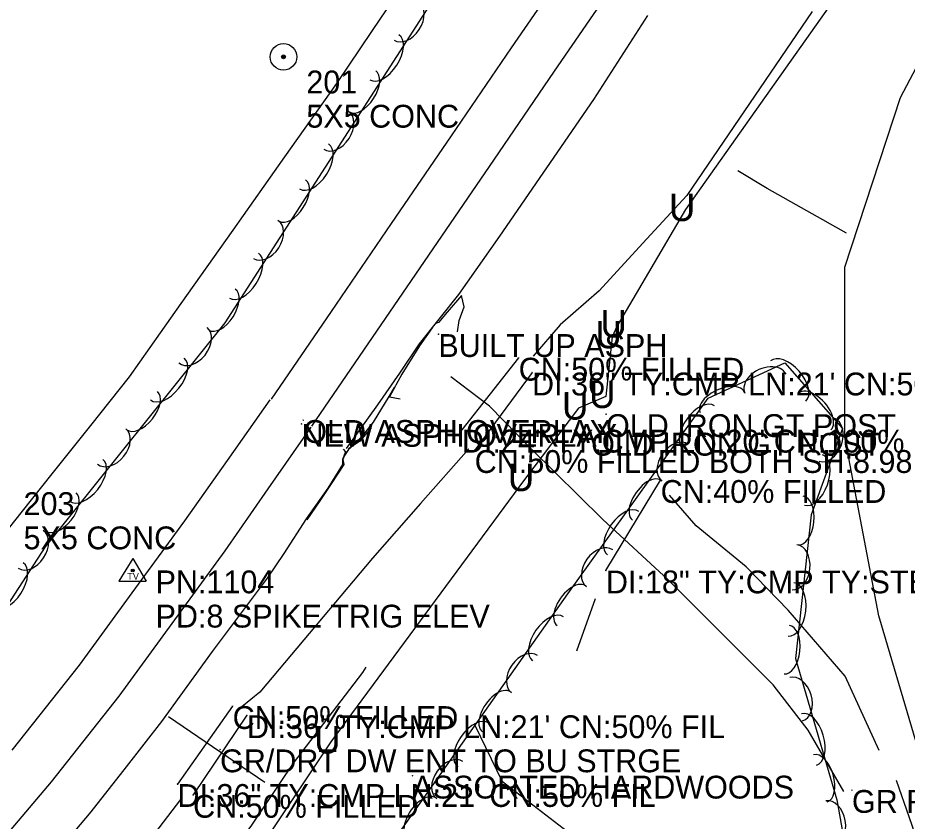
# Model space of a CAD drawing. Extents: x 1451369 to 1458940, y 1868647 to 1875095.
# Drawn here: x 1454748.2 to 1454943, y 1871825.9 to 1872001.9 of the extents above; entities that cross this region are included whole.
import ezdxf

# ---------------------------------------------------------------- set-up
doc = ezdxf.new("R2010")
doc.units = 0
for name, color, linetype in [('Default', 7, 'Continuous'), ('E_Const Align Station', 7, 'Continuous'), ('E_PL and Hook', 7, 'Continuous'), ('E_Proposed ROW and Easements', 7, 'Continuous'), ('E_ROW Point Number', 7, 'Continuous'), ('E_Station Offset', 7, 'Continuous'), ('E_Survey Point', 7, 'Continuous'), ('E_Survey Point Number', 7, 'Continuous'), ('E_Tract Number', 7, 'Continuous'), ('E_Tract Residual', 7, 'Continuous'), ('S_EDGE_PAVEMENT', 7, 'Continuous'), ('S_EXIST_ROW', 7, 'Continuous'), ('S_IRON_PIN_ANNOT', 7, 'Continuous'), ('S_MISC_BOUNDARY', 7, 'Continuous'), ('S_MISC_STRUCTURES_ANNOT', 7, 'Continuous'), ('S_PAVEMENT_CROWN', 7, 'Continuous'), ('S_SECONDARY_CTL_ANNOT', 7, 'Continuous'), ('S_SIDE_DRAIN_ANNOT', 7, 'Continuous'), ('S_SURVEY_TEXT_ANNOT', 7, 'Continuous'), ('S_TRAILS', 7, 'Continuous')]:
    doc.layers.add(name, color=color, linetype=linetype)

msp = doc.modelspace()

# ---------------------------------------------------------------- linework, layer by layer
at = {"layer": 'E_Const Align Station'}
for radius in [2.91, 0.411, 0.262, 0.212, 0.145, 0.0822, 0.0581]:
    msp.add_circle((1454806.43, 1871993.3), radius, dxfattribs=at)
at = {"layer": 'E_PL and Hook'}
for p, q in [((1454857.92, 1871927.4), (1454845.49, 1871911.64)), ((1454860.85, 1871924.16), (1454848.29, 1871907.18)), ((1454877.04, 1871880.81), (1454889.02, 1871900.62)), ((1454795.28, 1871851.11), (1454783.2, 1871834.04)), ((1454798.42, 1871849.1), (1454786.63, 1871831.67))]:
    msp.add_line(p, q, dxfattribs=at)
at = {"layer": 'E_Proposed ROW and Easements'}
for points in [[(1454840.33, 1871932.58), (1454840.33, 1871932.63), (1454840.33, 1871932.58), (1454840.28, 1871932.58), (1454840.33, 1871932.58), (1454840.33, 1871932.53), (1454840.33, 1871932.58), (1454840.38, 1871932.58)], [(1454877.05, 1871915.05), (1454877.05, 1871915.1), (1454877.05, 1871915.05), (1454877, 1871915.05), (1454877.05, 1871915.05), (1454877.05, 1871915), (1454877.05, 1871915.05), (1454877.1, 1871915.05)], [(1454810.37, 1871912.91), (1454810.37, 1871912.96), (1454810.37, 1871912.91), (1454810.32, 1871912.91), (1454810.37, 1871912.91), (1454810.37, 1871912.86), (1454810.37, 1871912.91), (1454810.42, 1871912.91)], [(1454810.75, 1871913.76), (1454810.75, 1871913.81), (1454810.75, 1871913.76), (1454810.7, 1871913.76), (1454810.75, 1871913.76), (1454810.75, 1871913.71), (1454810.75, 1871913.76), (1454810.8, 1871913.76)], [(1454873.8, 1871910.97), (1454873.8, 1871911.02), (1454873.8, 1871910.97), (1454873.75, 1871910.97), (1454873.8, 1871910.97), (1454873.8, 1871910.92), (1454873.8, 1871910.97), (1454873.85, 1871910.97)], [(1454848.31, 1871847), (1454848.31, 1871847.05), (1454848.31, 1871847), (1454848.26, 1871847), (1454848.31, 1871847), (1454848.31, 1871846.95), (1454848.31, 1871847), (1454848.36, 1871847)], [(1454792.53, 1871841.63), (1454792.53, 1871841.68), (1454792.53, 1871841.63), (1454792.48, 1871841.63), (1454792.53, 1871841.63), (1454792.53, 1871841.58), (1454792.53, 1871841.63), (1454792.58, 1871841.63)], [(1454834.64, 1871835.87), (1454834.64, 1871835.92), (1454834.64, 1871835.87), (1454834.59, 1871835.87), (1454834.64, 1871835.87), (1454834.64, 1871835.82), (1454834.64, 1871835.87), (1454834.69, 1871835.87)], [(1454854.39, 1871834.51), (1454854.39, 1871834.56), (1454854.39, 1871834.51), (1454854.34, 1871834.51), (1454854.39, 1871834.51), (1454854.39, 1871834.46), (1454854.39, 1871834.51), (1454854.44, 1871834.51)], [(1454930.91, 1871832.74), (1454930.91, 1871832.79), (1454930.91, 1871832.74), (1454930.86, 1871832.74), (1454930.91, 1871832.74), (1454930.91, 1871832.69), (1454930.91, 1871832.74), (1454930.96, 1871832.74)]]:
    msp.add_lwpolyline(points, dxfattribs=at)
at = {"layer": 'E_ROW Point Number'}
for points in [[(1454838.97, 1872005.51), (1454793.59, 1871935.04), (1454754.24, 1871885.99), (1454738.31, 1871861.57)], [(1454866, 1871710.55), (1454881.19, 1871720.56), (1454870.77, 1871731.38), (1454848.07, 1871733.96), (1454825.2, 1871735.11), (1454799.89, 1871732.45), (1454789.97, 1871746.64), (1454796, 1871772.6), (1454868.67, 1871875.67), (1454899.4, 1871918.58), (1454916.25, 1871926.31), (1454928.84, 1871911.94), (1454921.96, 1871892.98), (1454918.57, 1871861.56), (1454927.6, 1871830.59), (1454936.01, 1871783.4), (1454940.39, 1871738.54), (1454943.46, 1871701.76)]]:
    msp.add_lwpolyline(points, dxfattribs=at)
for centre, major_axis, ratio, start_param, end_param in [((1454833.31, 1872001.13), (2.68, 4.17), 0.68525, 3.141593, 6.283185), ((1454828.52, 1871993.21), (3.18, 4.93), 0.550031, 3.141593, 6.283185), ((1454823.72, 1871985.75), (2.89, 4.5), 0.540651, 3.141593, 6.283185), ((1454817.92, 1871977.23), (2.68, 4.17), 0.68525, 3.141593, 6.283185), ((1454813.13, 1871969.3), (3.18, 4.93), 0.550031, 3.141593, 6.283185), ((1454808.33, 1871961.85), (2.89, 4.5), 0.540651, 3.141593, 6.283185), ((1454802.53, 1871953.33), (2.68, 4.17), 0.68525, 3.141593, 6.283185), ((1454797.74, 1871945.4), (3.18, 4.93), 0.550031, 3.141593, 6.283185), ((1454792.94, 1871937.95), (2.89, 4.5), 0.540651, 3.141593, 6.283185), ((1454786.59, 1871930.13), (3.1, 3.87), 0.685257, 3.141593, 6.283185), ((1454781, 1871922.74), (3.67, 4.58), 0.550037, 3.141593, 6.283185), ((1454916.93, 1871922.31), (-3.87, 4.41), 0.5501, 3.141567, 6.283159), ((1454911.97, 1871921.72), (-4.5, -2.07), 0.685217, 3.141379, 6.282972), ((1454902.5, 1871917.66), (-4.86, -2.23), 0.540626, 3.141466, 6.283059), ((1454922.77, 1871915.64), (-3.52, 4.02), 0.54072, 3.141567, 6.28316), ((1454775.45, 1871915.82), (3.35, 4.17), 0.540657, 3.141593, 6.283185), ((1454897.38, 1871912.11), (-3.42, -4.77), 0.550059, 3.141794, 6.283386), ((1454925.4, 1871909.44), (1.69, 4.66), 0.685239, 3.141593, 6.283185), ((1454768.8, 1871907.95), (3.1, 3.87), 0.685257, 3.141593, 6.283185), ((1454892.2, 1871904.43), (-2.89, -4.03), 0.685285, 3.141922, 6.283514), ((1454763.21, 1871900.57), (3.67, 4.58), 0.550037, 3.141593, 6.283185), ((1454922.49, 1871900.65), (2, 5.52), 0.550022, 3.141593, 6.283185), ((1454885.99, 1871896.21), (-3.11, -4.35), 0.540679, 3.141787, 6.28338), ((1454757.67, 1871893.65), (3.35, 4.17), 0.540657, 3.141593, 6.283185), ((1454919.69, 1871891.74), (0.57, 5.32), 0.540665, 3.141593, 6.283185), ((1454880.83, 1871889), (-3.42, -4.77), 0.550059, 3.141794, 6.283386), ((1454751.05, 1871885.46), (2.71, 4.15), 0.68525, 3.141593, 6.283185), ((1454875.65, 1871881.32), (-2.89, -4.03), 0.685285, 3.141922, 6.283514), ((1454918.33, 1871881.52), (0.53, 4.93), 0.685268, 3.141593, 6.283185), ((1454746.21, 1871877.56), (3.21, 4.92), 0.550031, 3.141593, 6.283185), ((1454869.46, 1871873.11), (-3.08, -4.37), 0.540631, 3.141676, 6.283269), ((1454917.59, 1871872.29), (0.63, 5.83), 0.550045, 3.141593, 6.283185), ((1454864.35, 1871865.86), (-3.38, -4.8), 0.55001, 3.141679, 6.283271), ((1454916.64, 1871863.47), (0.57, 5.32), 0.540665, 3.141593, 6.283185), ((1454859.22, 1871858.14), (-2.86, -4.05), 0.685224, 3.141734, 6.283326), ((1454918.69, 1871852.63), (-1.39, 4.76), 0.685303, 3.141593, 6.283185), ((1454853.07, 1871849.87), (-3.08, -4.37), 0.540631, 3.141676, 6.283269), ((1454921.53, 1871843.82), (-1.64, 5.63), 0.550074, 3.141593, 6.283185), ((1454847.97, 1871842.62), (-3.38, -4.8), 0.55001, 3.141679, 6.283271), ((1454924.01, 1871835.3), (-1.5, 5.13), 0.540694, 3.141593, 6.283185), ((1454842.84, 1871834.91), (-2.86, -4.05), 0.685224, 3.141734, 6.283326), ((1454836.69, 1871826.64), (-3.08, -4.37), 0.540631, 3.141676, 6.283269), ((1454926.09, 1871825.47), (-0.87, 4.88), 0.685298, 3.141572, 6.283164)]:
    msp.add_ellipse(centre, major_axis=major_axis, ratio=ratio, start_param=start_param, end_param=end_param, dxfattribs=at)
at = {"layer": 'E_Station Offset'}
for p, q in [((1454773.4, 1871883.43), (1454770.39, 1871878.47)), ((1454773.4, 1871883.43), (1454776.35, 1871878.47)), ((1454770.39, 1871878.47), (1454776.35, 1871878.47))]:
    msp.add_line(p, q, dxfattribs=at)
for radius in [0.311, 0.183, 0.103]:
    msp.add_circle((1454773.4, 1871880.82), radius, dxfattribs=at)
at = {"layer": 'E_Survey Point'}
for p, q in [((1454854.39, 1871834.51), (1454848.31, 1871847)), ((1454880.25, 1871814.68), (1454854.39, 1871834.51))]:
    msp.add_line(p, q, dxfattribs=at)
at = {"layer": 'E_Survey Point Number'}
for p, q in [((1455036.45, 1872160.65), (1454894.46, 1871959.88)), ((1454894.46, 1871959.88), (1454879.47, 1871934.42)), ((1454879.47, 1871934.42), (1454878.37, 1871932.01)), ((1454878.37, 1871932.01), (1454876.98, 1871918.94)), ((1454876.98, 1871918.94), (1454871.04, 1871916.4)), ((1454871.04, 1871916.4), (1454859.19, 1871900.75)), ((1454859.19, 1871900.75), (1454816.77, 1871843.27)), ((1454816.77, 1871843.27), (1454794.83, 1871810.44))]:
    msp.add_line(p, q, dxfattribs=at)
at = {"layer": 'E_Tract Number'}
for points in [[(1454857.92, 1871927.4), (1454857.92, 1871927.45), (1454857.92, 1871927.4), (1454857.87, 1871927.4), (1454857.92, 1871927.4), (1454857.92, 1871927.35), (1454857.92, 1871927.4), (1454857.97, 1871927.4)], [(1454860.85, 1871924.16), (1454860.85, 1871924.21), (1454860.85, 1871924.16), (1454860.8, 1871924.16), (1454860.85, 1871924.16), (1454860.85, 1871924.11), (1454860.85, 1871924.16), (1454860.9, 1871924.16)], [(1454845.49, 1871911.64), (1454845.49, 1871911.69), (1454845.49, 1871911.64), (1454845.44, 1871911.64), (1454845.49, 1871911.64), (1454845.49, 1871911.59), (1454845.49, 1871911.64), (1454845.54, 1871911.64)], [(1454848.29, 1871907.18), (1454848.29, 1871907.23), (1454848.29, 1871907.18), (1454848.24, 1871907.18), (1454848.29, 1871907.18), (1454848.29, 1871907.13), (1454848.29, 1871907.18), (1454848.34, 1871907.18)], [(1454889.02, 1871900.62), (1454889.02, 1871900.67), (1454889.02, 1871900.62), (1454888.97, 1871900.62), (1454889.02, 1871900.62), (1454889.02, 1871900.57), (1454889.02, 1871900.62), (1454889.07, 1871900.62)], [(1454877.04, 1871880.81), (1454877.04, 1871880.86), (1454877.04, 1871880.81), (1454876.99, 1871880.81), (1454877.04, 1871880.81), (1454877.04, 1871880.76), (1454877.04, 1871880.81), (1454877.09, 1871880.81)], [(1454795.28, 1871851.11), (1454795.28, 1871851.16), (1454795.28, 1871851.11), (1454795.23, 1871851.11), (1454795.28, 1871851.11), (1454795.28, 1871851.06), (1454795.28, 1871851.11), (1454795.33, 1871851.11)], [(1454798.42, 1871849.1), (1454798.42, 1871849.15), (1454798.42, 1871849.1), (1454798.37, 1871849.1), (1454798.42, 1871849.1), (1454798.42, 1871849.05), (1454798.42, 1871849.1), (1454798.47, 1871849.1)], [(1454783.2, 1871834.04), (1454783.2, 1871834.09), (1454783.2, 1871834.04), (1454783.15, 1871834.04), (1454783.2, 1871834.04), (1454783.2, 1871833.99), (1454783.2, 1871834.04), (1454783.25, 1871834.04)], [(1454786.63, 1871831.67), (1454786.63, 1871831.72), (1454786.63, 1871831.67), (1454786.58, 1871831.67), (1454786.63, 1871831.67), (1454786.63, 1871831.62), (1454786.63, 1871831.67), (1454786.68, 1871831.67)]]:
    msp.add_lwpolyline(points, dxfattribs=at)
at = {"layer": 'E_Tract Residual'}
msp.add_lwpolyline([(1454958.72, 1871739.79), (1454951.87, 1871790.34), (1454946.35, 1871818.45), (1454940.67, 1871834.81)], dxfattribs=at)
at = {"layer": 'S_EDGE_PAVEMENT'}
for points in [[(1454869.28, 1872014.16), (1454856.27, 1871995.25), (1454843.13, 1871976.02), (1454829.99, 1871956.78), (1454816.85, 1871937.55), (1454803.72, 1871918.32)], [(1454886.12, 1872002.39), (1454874.32, 1871984), (1454864.04, 1871969), (1454853.75, 1871954.01), (1454844.75, 1871941.26), (1454836.1, 1871930.43), (1454831.8, 1871924.05), (1454826.99, 1871917.08), (1454820.11, 1871907.56)], [(1454844.54, 1871933.1), (1454844.87, 1871935.55), (1454845.96, 1871938.55), (1454845.43, 1871941.03), (1454842.29, 1871937.39), (1454840.38, 1871935.15), (1454839.74, 1871934.92)], [(1454838.98, 1871933.96), (1454836.17, 1871930), (1454832.36, 1871923.82), (1454829.6, 1871918.83), (1454831.99, 1871918.44)], [(1454830.65, 1871920.86), (1454829.46, 1871918.93), (1454826.04, 1871913.27), (1454823.43, 1871909.96), (1454821.73, 1871908.37), (1454820.62, 1871907.42)], [(1454803.44, 1871918.16), (1454794.09, 1871904.94), (1454784.73, 1871891.72), (1454773.21, 1871875.91), (1454761.69, 1871860.1), (1454746.95, 1871841.48)], [(1454825.59, 1871912.09), (1454823.03, 1871909.09), (1454821.64, 1871908.11), (1454820.68, 1871907.33), (1454819.81, 1871906.03), (1454819.44, 1871905.12), (1454819.6, 1871904.02), (1454816.86, 1871899.83), (1454814.4, 1871896.06), (1454811.51, 1871891.9)], [(1454819.52, 1871907.39), (1454820.03, 1871906.78), (1454819.34, 1871905.12), (1454819.31, 1871904.02), (1454816.14, 1871898.87), (1454811.41, 1871892.12), (1454806.52, 1871884.57), (1454802.87, 1871879.15), (1454790.82, 1871863.04), (1454779.71, 1871847.75), (1454771.96, 1871837.84), (1454764.21, 1871827.94), (1454754.88, 1871816.87), (1454745.54, 1871805.81)]]:
    msp.add_lwpolyline(points, dxfattribs=at)
at = {"layer": 'S_EXIST_ROW'}
for points in [[(1454707.96, 1871838.25), (1454715.68, 1871848.85), (1454723.41, 1871859.46), (1454731.14, 1871870.06), (1454738.87, 1871880.67), (1454747.32, 1871891.31), (1454755.77, 1871901.96), (1454764.23, 1871912.6), (1454772.68, 1871923.25), (1454784.03, 1871939.3), (1454795.39, 1871955.35), (1454806.74, 1871971.41), (1454818.1, 1871987.46), (1454825.89, 1871999.07), (1454833.69, 1872010.69), (1454841.48, 1872022.3), (1454849.28, 1872033.91)], [(1454922.21, 1872003.26), (1454908.47, 1871983.1), (1454894.72, 1871962.93), (1454885.13, 1871952.51), (1454875.53, 1871942.08), (1454867.01, 1871934.65), (1454861.12, 1871927.73)], [(1454929.71, 1871954.66), (1454912.31, 1871964.45), (1454905.92, 1871968.34)], [(1454847, 1871907.48), (1454836.45, 1871895.48), (1454825.89, 1871883.49), (1454813.57, 1871868.84), (1454801.24, 1871854.19), (1454797.33, 1871850.99)], [(1454936.87, 1871841.38), (1454929.44, 1871857.7), (1454916.93, 1871872.12), (1454907.75, 1871881.64), (1454896.76, 1871890.63), (1454890.95, 1871897.32)], [(1454870.67, 1871863.22), (1454874.75, 1871874.69)], [(1454824.42, 1871859.67), (1454823.71, 1871858.48), (1454808.54, 1871838.61), (1454799.29, 1871824.85), (1454791.96, 1871815.26), (1454785.65, 1871808.4)], [(1454783.87, 1871830.65), (1454773.41, 1871816.98), (1454765.55, 1871805.47), (1454757.7, 1871793.95)]]:
    msp.add_lwpolyline(points, dxfattribs=at)
at = {"layer": 'S_MISC_BOUNDARY'}
msp.add_lwpolyline([(1454968.19, 1871712.29), (1454955.87, 1871795.22), (1454948.77, 1871830.35), (1454936.8, 1871870.9), (1454929.34, 1871910.01), (1454929.36, 1871947.22), (1454941.55, 1871984.39), (1454964.58, 1872028.21), (1455009.26, 1872095.69), (1455071.49, 1872183.66), (1455110.31, 1872228.42), (1455136.38, 1872254.42), (1455148.95, 1872271.07), (1455155.24, 1872298.12), (1455196.69, 1872380.74)], dxfattribs=at)
at = {"layer": 'S_PAVEMENT_CROWN'}
for points in [[(1454878.1, 1872008.25), (1454865.71, 1871990.14), (1454852.42, 1871970.71), (1454839.12, 1871951.28), (1454825.82, 1871931.85), (1454812.53, 1871912.42)], [(1454929.12, 1871832.43), (1454921.36, 1871845.82), (1454913.68, 1871855.78), (1454902.15, 1871867.28), (1454890.63, 1871878.79), (1454876.25, 1871892.06), (1454860.7, 1871907.36), (1454851.56, 1871916.81), (1454843.09, 1871923.2)], [(1454812.39, 1871912.2), (1454802.99, 1871898.68), (1454793.59, 1871885.15), (1454781.98, 1871869.23), (1454770.38, 1871853.31), (1454755.56, 1871834.56), (1454746.72, 1871824.06)]]:
    msp.add_lwpolyline(points, dxfattribs=at)
at = {"layer": 'S_TRAILS'}
msp.add_lwpolyline([(1454802.3, 1871834.4), (1454781.25, 1871848.75)], dxfattribs=at)

# ---------------------------------------------------------------- texts
at = {"layer": 'Default'}
for p in [(1454890.83, 1871957.34), (1454875.84, 1871931.87), (1454874.74, 1871929.47), (1454873.35, 1871916.39), (1454867.41, 1871913.86), (1454855.56, 1871898.21), (1454813.14, 1871840.73)]:
    msp.add_text('U', height=6, rotation=360, dxfattribs=at).set_placement(p)
at = {"layer": 'E_Station Offset'}
msp.add_text('TV', height=1.5, rotation=360, dxfattribs=at).set_placement((1454772.2, 1871878.8))
at = {"layer": 'S_IRON_PIN_ANNOT'}
for s, p in [('201', (1454811.43, 1871985.3)), ('5X5 CONC', (1454811.43, 1871977.8)), ('203', (1454749.49, 1871892.96)), ('5X5 CONC', (1454749.49, 1871885.46))]:
    msp.add_text(s, height=5, dxfattribs=at).set_placement(p)
at = {"layer": 'S_MISC_STRUCTURES_ANNOT'}
for p in [(1454877.05, 1871910.05), (1454873.8, 1871905.97)]:
    msp.add_text('OLD IRON GT POST', height=5, dxfattribs=at).set_placement(p)
at = {"layer": 'S_SECONDARY_CTL_ANNOT'}
for s, p in [('PN:1104', (1454778.4, 1871875.82)), ('PD:8 SPIKE TRIG ELEV', (1454778.4, 1871868.32))]:
    msp.add_text(s, height=5, dxfattribs=at).set_placement(p)
at = {"layer": 'S_SIDE_DRAIN_ANNOT'}
for s, p in [('CN:50% FILLED', (1454857.92, 1871922.4)), ('DI:36" TY:CMP LN:21\' CN:50% FIL', (1454860.85, 1871919.16)), ('DI:24" TY:CMP LN:20\' CN:100% FI', (1454845.49, 1871906.64)), ('CN:50% FILLED BOTH SH:8.98', (1454848.29, 1871902.18)), ('CN:40% FILLED', (1454889.02, 1871895.62)), ('DI:18" TY:CMP TY:STEEL LN:23\' C', (1454877.04, 1871875.81)), ('CN:50% FILLED', (1454795.28, 1871846.11)), ('DI:36" TY:CMP LN:21\' CN:50% FIL', (1454798.42, 1871844.1)), ('DI:36" TY:CMP LN:21\' CN:50% FIL', (1454783.2, 1871829.04)), ('CN:50% FILLED', (1454786.63, 1871826.67))]:
    msp.add_text(s, height=5, dxfattribs=at).set_placement(p)
at = {"layer": 'S_SURVEY_TEXT_ANNOT'}
for s, p in [('BUILT UP ASPH', (1454840.33, 1871927.58)), ('NEW ASPH OVERLAY', (1454810.37, 1871907.91)), ('OLD ASPH OVERLAY', (1454810.75, 1871908.76)), ('GR/DRT DW ENT TO BU STRGE', (1454792.53, 1871836.63)), ('ASSORTED HARDWOODS', (1454834.64, 1871830.87)), ('GR RD ENT TO FARM FIELD', (1454930.91, 1871827.74))]:
    msp.add_text(s, height=5, dxfattribs=at).set_placement(p)

doc.saveas('drawing.dxf')
